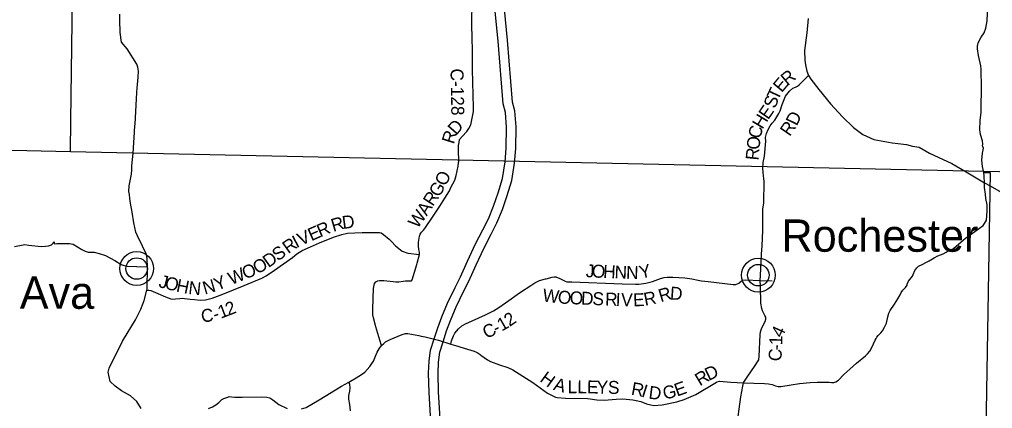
# Model space of a CAD drawing. Extents: x 0 to 34, y 0 to 22.
# Drawn here: x 24.277 to 28.547, y 13.16 to 14.868 of the extents above; entities that cross this region are included whole.
import ezdxf

# ---------------------------------------------------------------- set-up
doc = ezdxf.new("R2010")
doc.units = 0
for name, color, linetype in [('Default', 7, 'Continuous'), ('GM_X_County_Road', 7, 'Continuous'), ('GM_X_County_Road_Text', 7, 'Continuous'), ('GM_X_State_Route', 7, 'Continuous'), ('GM_X_Township', 7, 'Continuous'), ('GM_X_Unincorporated', 7, 'Continuous'), ('GM_X_Unincorporated_Text', 7, 'Continuous')]:
    doc.layers.add(name, color=color, linetype=linetype)

msp = doc.modelspace()

# ---------------------------------------------------------------- linework, layer by layer
at = {"layer": 'Default'}
for points in [[(28.5032, 14.3125), (28.5032, 14.3126), (28.5041, 14.3199), (28.5022, 14.335), (28.4942, 14.363), (28.4916, 14.3835), (28.493, 14.424), (28.4964, 14.4614), (28.4975, 14.4788), (28.4982, 14.5681), (28.497, 14.6499), (28.4955, 14.6639), (28.4856, 14.7097), (28.4811, 14.7392), (28.4811, 14.7513), (28.4837, 14.7653), (28.4973, 14.7899), (28.5094, 14.8088), (28.518, 14.8297), (28.5237, 14.8622), (28.5275, 14.9622)], [(26.2042, 14.2401), (26.2048, 14.2448), (26.2031, 14.2953), (26.2034, 14.3146), (26.2066, 14.3276), (26.2081, 14.3407), (26.2197, 14.3548), (26.2399, 14.3765), (26.2493, 14.3899), (26.2571, 14.4058), (26.2608, 14.4199), (26.2662, 14.4494), (26.2688, 14.4635), (26.2698, 14.482), (26.2656, 14.6481), (26.2646, 14.7424), (26.2636, 14.7768), (26.2626, 14.854), (26.2639, 14.943)], [(28.5119, 14.1501), (28.5105, 14.1807), (28.5081, 14.1966), (28.5023, 14.2231), (28.4995, 14.2499), (28.5028, 14.2814), (28.5066, 14.3028), (28.5032, 14.3125)], [(26.0228, 13.7982), (26.0229, 13.7985), (26.0329, 13.8366), (26.0329, 13.8461), (26.0297, 13.8582), (26.0277, 13.8744), (26.0284, 13.8896), (26.0309, 13.9078), (26.032, 13.9169), (26.0349, 13.9252), (26.0409, 13.934), (26.0503, 13.9431), (26.0589, 13.9542), (26.0899, 14.0002), (26.1213, 14.0489), (26.1434, 14.0839), (26.1639, 14.1159), (26.1699, 14.1296), (26.1873, 14.1621), (26.1931, 14.1827), (26.2021, 14.2237), (26.2042, 14.2401)], [(27.4545, 13.2725), (27.4579, 13.2805), (27.473, 13.3025), (27.5017, 13.3453), (27.5186, 13.3688), (27.5213, 13.3741), (27.5232, 13.3904), (27.5268, 13.4843), (27.5287, 13.4968), (27.5344, 13.5138), (27.5498, 13.5426), (27.5514, 13.5521), (27.5521, 13.5608), (27.5483, 13.5687), (27.5377, 13.5888), (27.5339, 13.5997), (27.5301, 13.6228), (27.5293, 13.6966), (27.5278, 13.7224), (27.5293, 13.7436), (27.5333, 13.8378), (27.536, 13.8745), (27.5389, 13.9415), (27.5392, 14.0346), (27.544, 14.0631), (27.5446, 14.1573), (27.544, 14.1704), (27.5425, 14.1812), (27.5399, 14.1968)], [(28.5158, 14.1005), (28.5121, 14.1308), (28.5119, 14.1501)], [(27.4545, 13.2725), (27.4995, 13.2711), (27.5463, 13.2693), (27.5644, 13.2682), (27.5796, 13.2652), (27.5951, 13.2603), (27.6064, 13.2572), (27.6177, 13.2569), (27.6631, 13.2634), (27.6993, 13.2699), (27.7473, 13.2737), (27.7772, 13.2764), (27.7991, 13.2761), (27.8293, 13.2754), (27.8407, 13.2739), (27.8509, 13.275), (27.8592, 13.2777), (27.8705, 13.2845), (27.8947, 13.3088), (27.9211, 13.3331), (27.9502, 13.3592), (27.9894, 13.3915), (27.9985, 13.4009), (28.0087, 13.4123), (28.0174, 13.4275), (28.0313, 13.4597), (28.0355, 13.468), (28.0389, 13.4733), (28.0453, 13.4809), (28.0574, 13.4923), (28.0645, 13.5006), (28.0732, 13.5169), (28.0815, 13.5355), (28.0879, 13.5623), (28.0924, 13.5786), (28.0973, 13.5904), (28.117, 13.6184), (28.1313, 13.6415), (28.1415, 13.6593), (28.1464, 13.6692), (28.1539, 13.6794), (28.1653, 13.6915), (28.1721, 13.7014), (28.1724, 13.7067), (28.1781, 13.7192), (28.1955, 13.7415), (28.1988, 13.748), (28.206, 13.7658), (28.2143, 13.7775), (28.2215, 13.7855), (28.2374, 13.7927), (28.2577, 13.8029), (28.2687, 13.8079), (28.291, 13.8215), (28.3065, 13.8299), (28.3189, 13.8352), (28.3303, 13.8394), (28.3439, 13.8466), (28.3526, 13.8519), (28.3665, 13.8584), (28.3756, 13.8629), (28.3877, 13.8735), (28.4285, 13.9077), (28.459, 13.9304), (28.49, 13.9513), (28.5055, 13.9638), (28.5123, 13.9729), (28.5205, 13.9874), (28.5224, 14.0065), (28.5233, 14.0275), (28.5233, 14.0542), (28.5181, 14.0814), (28.5158, 14.1005)], [(24.8361, 13.6794), (24.845, 13.68), (24.8533, 13.6781), (24.8837, 13.6652), (24.9181, 13.651), (24.9409, 13.6417), (24.9503, 13.6407), (24.9613, 13.6411), (24.9809, 13.6436), (24.9915, 13.6444), (25.0017, 13.643), (25.0149, 13.6416), (25.0259, 13.6405), (25.0452, 13.638), (25.0705, 13.6356), (25.0932, 13.6372), (25.123, 13.6447), (25.1689, 13.6617), (25.2627, 13.7007), (25.3407, 13.7323), (25.3596, 13.7423), (25.3956, 13.768), (25.4746, 13.8231), (25.4945, 13.8392), (25.5182, 13.8534), (25.5547, 13.8692), (25.5943, 13.8873), (25.6549, 13.9127), (25.6923, 13.9244), (25.7168, 13.9303), (25.7806, 13.9334), (25.8569, 13.9325), (25.8638, 13.9307), (25.8744, 13.9239), (25.8998, 13.9033), (25.9097, 13.8939), (25.9276, 13.8736), (25.9561, 13.8511), (25.9807, 13.8415), (26.0329, 13.8366)], [(24.255, 13.871), (24.293, 13.8792), (24.2991, 13.8801), (24.3188, 13.8774), (24.3726, 13.8715), (24.3911, 13.8723), (24.4043, 13.8736), (24.4178, 13.8784), (24.4299, 13.8915), (24.4298, 13.8832), (24.4404, 13.8841), (24.4971, 13.8851), (24.5043, 13.8834), (24.513, 13.8809), (24.5512, 13.8581), (24.5653, 13.8504), (24.5779, 13.8464), (24.5911, 13.8463), (24.6043, 13.8465), (24.6267, 13.8405), (24.6545, 13.8323), (24.6957, 13.8095), (24.7232, 13.793), (24.7316, 13.789), (24.7423, 13.7867), (24.7494, 13.7851), (24.7909, 13.7839), (24.8386, 13.7826)], [(25.8654, 13.4374), (25.858, 13.4604), (25.8413, 13.5194), (25.8309, 13.5579), (25.8278, 13.5707), (25.8272, 13.5931), (25.8288, 13.6438), (25.8311, 13.6874), (25.8355, 13.709), (25.8403, 13.7166), (25.8494, 13.7212), (25.8569, 13.7228), (25.8758, 13.7222), (25.9163, 13.718), (25.9291, 13.7165), (25.9423, 13.7163), (25.9612, 13.7198), (25.9706, 13.7207), (25.9873, 13.7208), (25.9948, 13.7201), (25.9971, 13.7212), (26.0005, 13.7251), (26.0211, 13.7919), (26.0228, 13.7982)], [(26.17, 13.4432), (26.1722, 13.4566), (26.1809, 13.4791), (26.1875, 13.4913), (26.2031, 13.5094), (26.2176, 13.5225), (26.2344, 13.5323), (26.3222, 13.5718), (26.3566, 13.5894), (26.3802, 13.6035), (26.4243, 13.6342), (26.4605, 13.6599), (26.4758, 13.6707), (26.5203, 13.7007), (26.5378, 13.7112), (26.5596, 13.7215), (26.5859, 13.7291), (26.5881, 13.7297)], [(26.5881, 13.7297), (26.6141, 13.7372), (26.6235, 13.7385), (26.6303, 13.7379), (26.6475, 13.7302), (26.6719, 13.719), (26.6787, 13.7168), (26.7014, 13.7165), (26.9215, 13.7076), (26.9809, 13.7056), (26.9948, 13.7066), (27.0254, 13.711), (27.0547, 13.7176), (27.0896, 13.7314), (27.1055, 13.7355), (27.1198, 13.7373), (27.1447, 13.7374), (27.1962, 13.7337), (27.2272, 13.7301), (27.2557, 13.7235), (27.2694, 13.7199), (27.2993, 13.7171), (27.4083, 13.705), (27.4208, 13.7052), (27.4332, 13.7104), (27.4459, 13.7201), (27.4518, 13.724), (27.4643, 13.7253), (27.5278, 13.7224)], [(27.5278, 13.7224), (27.5801, 13.72)], [(25.5146, 13.1582), (25.5347, 13.1647), (25.5924, 13.1985), (25.6906, 13.2577), (25.7224, 13.2759), (25.7548, 13.2949), (25.7786, 13.3093), (25.7922, 13.3199), (25.8145, 13.3449), (25.8239, 13.3574), (25.8311, 13.3681), (25.8394, 13.3893), (25.8473, 13.4078), (25.856, 13.4222), (25.8654, 13.4374), (25.8752, 13.4457), (25.8828, 13.4526), (25.9032, 13.4636), (25.9564, 13.4856), (25.9704, 13.4898), (25.9806, 13.4894), (26.0294, 13.4804), (26.0403, 13.478), (26.0403, 13.478)], [(26.0403, 13.478), (26.0566, 13.4744), (26.0683, 13.4718), (26.1162, 13.4597), (26.17, 13.4432), (26.1904, 13.4364), (26.2425, 13.4213), (26.2724, 13.4115), (26.2849, 13.4059), (26.2983, 13.3967), (26.2984, 13.3967)], [(26.2984, 13.3967), (26.3015, 13.3945), (26.3314, 13.3734), (26.3442, 13.3662), (26.3836, 13.3523), (26.4198, 13.3406), (26.4414, 13.33), (26.5291, 13.2745), (26.5941, 13.2273), (26.6172, 13.2152), (26.6289, 13.2103), (26.6372, 13.2081), (26.6735, 13.2062), (26.7699, 13.2041), (26.782, 13.2022), (26.8099, 13.1981), (26.8432, 13.1963), (26.8949, 13.2005), (26.9248, 13.2021), (26.969, 13.198), (26.983, 13.1953), (27.0034, 13.1908), (27.0291, 13.1814), (27.0469, 13.1765), (27.0601, 13.1739), (27.0967, 13.1762), (27.1613, 13.1888), (27.1938, 13.1994), (27.2456, 13.2215), (27.3358, 13.2758), (27.3392, 13.2773), (27.3491, 13.2803), (27.3978, 13.2755), (27.4545, 13.2725)], [(25.73, 13.1506), (25.7262, 13.1782), (25.722, 13.2017), (25.7217, 13.2078), (25.7228, 13.2172), (25.7269, 13.2358), (25.7288, 13.2509), (25.7265, 13.2649), (25.7224, 13.2759)], [(27.4241, 13.0703), (27.4425, 13.2112), (27.4511, 13.2578), (27.4545, 13.2725)], [(25.1062, 13.1599), (25.1239, 13.1675), (25.139, 13.177), (25.1526, 13.1872), (25.1583, 13.1929), (25.1658, 13.2001), (25.1734, 13.2046), (25.1908, 13.2107), (25.1968, 13.2122), (25.207, 13.2111), (25.2221, 13.2104), (25.2546, 13.2104), (25.3389, 13.2113), (25.3631, 13.2095), (25.3759, 13.2065), (25.3888, 13.1985), (25.4145, 13.1777), (25.4515, 13.16)]]:
    msp.add_lwpolyline(points, dxfattribs=at)
at = {"layer": 'GM_X_County_Road'}
msp.add_lwpolyline([(27.5399, 14.1968), (27.5398, 14.1975), (27.5396, 14.2134), (27.54, 14.2407), (27.5457, 14.2678), (27.5518, 14.3336), (27.5511, 14.3499), (27.5545, 14.3673), (27.562, 14.3855), (27.5707, 14.4007), (27.5805, 14.4132), (27.5911, 14.426), (27.6088, 14.4556), (27.6156, 14.4673), (27.6231, 14.4942), (27.6386, 14.5317), (27.6556, 14.5529), (27.6699, 14.5658), (27.682, 14.5704), (27.6907, 14.5753), (27.6986, 14.5814), (27.7171, 14.5995), (27.7398, 14.6223)], dxfattribs=at)
at = {"layer": 'GM_X_State_Route'}
for points in [[(26.0897, 12.974), (26.0747, 13.2305), (26.0725, 13.3149), (26.0742, 13.3676), (26.0805, 13.4164), (26.0964, 13.4661), (26.1123, 13.5144), (26.1302, 13.5623), (26.1557, 13.6232), (26.1882, 13.692), (26.2119, 13.738), (26.2435, 13.8076), (26.2788, 13.8837), (26.3097, 13.9438), (26.3345, 13.9933), (26.3576, 14.0485), (26.377, 14.1076), (26.3963, 14.1697), (26.4079, 14.2426), (26.4129, 14.3035), (26.4145, 14.3949), (26.4102, 14.4596), (26.3993, 14.4976), (26.3777, 14.7733), (26.3443, 15.1077)], [(26.1312, 12.9764), (26.1162, 13.2323), (26.1141, 13.3147), (26.1157, 13.3643), (26.1212, 13.4073), (26.1359, 13.4533), (26.1515, 13.5006), (26.1689, 13.547), (26.1937, 13.6063), (26.2255, 13.6736), (26.2493, 13.7198), (26.2813, 13.7902), (26.3162, 13.8655), (26.3468, 13.925), (26.3724, 13.9759), (26.3966, 14.034), (26.4166, 14.0949), (26.4369, 14.1603), (26.4492, 14.2376), (26.4545, 14.3014), (26.4561, 14.3959), (26.4514, 14.4667), (26.4404, 14.505), (26.4192, 14.7769), (26.3858, 15.111)], [(24.7697, 14.2083), (24.7708, 14.2253), (24.7757, 14.2814), (24.7808, 14.3493), (24.7838, 14.401), (24.785, 14.4089), (24.7921, 14.5479), (24.7942, 14.5684), (24.7953, 14.5823), (24.7979, 14.6139), (24.7995, 14.6402), (24.7958, 14.6583), (24.7918, 14.6711), (24.7493, 14.7395), (24.7246, 14.7685), (24.7184, 14.8109), (24.7174, 14.8651), (24.7179, 14.8913)], [(27.7378, 14.8727), (27.7316, 14.8094), (27.7224, 14.732), (27.723, 14.6896), (27.7257, 14.668), (27.7326, 14.6412), (27.7398, 14.6223), (27.7492, 14.6064), (27.784, 14.5599), (27.8354, 14.4973), (27.8883, 14.4403), (27.9365, 14.3936), (27.9779, 14.3627), (28.0257, 14.3413), (28.1064, 14.3262), (28.17, 14.3189), (28.1951, 14.3122), (28.2246, 14.3074), (28.2705, 14.2804), (28.3687, 14.2356), (28.4305, 14.1984), (28.5119, 14.1501), (28.536, 14.137), (28.6503, 14.0719)], [(24.8197, 13.6229), (24.8243, 13.6349), (24.8361, 13.6794), (24.8378, 13.6857), (24.8386, 13.7826), (24.8372, 13.8179), (24.8353, 13.8277), (24.8331, 13.8389), (24.8173, 13.8728), (24.8151, 13.8768), (24.8017, 13.9016), (24.7884, 13.9337), (24.7787, 13.9757), (24.771, 14.0223), (24.7649, 14.0615), (24.7617, 14.0814), (24.7593, 14.0991), (24.7576, 14.1121), (24.7588, 14.137), (24.7601, 14.1455), (24.7683, 14.189), (24.7697, 14.2083)], [(24.811, 13.1596), (24.7927, 13.1909), (24.7642, 13.2158), (24.7255, 13.238), (24.697, 13.2583), (24.6754, 13.2791), (24.6666, 13.319), (24.6703, 13.3372), (24.7285, 13.4559), (24.786, 13.5494), (24.8093, 13.5962), (24.8197, 13.6229)]]:
    msp.add_lwpolyline(points, dxfattribs=at)
at = {"layer": 'GM_X_Township'}
for p, q in [((24.5027, 14.424), (24.5114, 15.0682)), ((24.5006, 14.2876), (24.5027, 14.424)), ((23.5089, 14.3112), (24.5006, 14.2876)), ((24.5006, 14.2876), (30.697, 14.1555)), ((28.5367, 14.1959), (28.456, 9.6182)), ((28.5081, 14.1966), (28.5367, 14.1959)), ((28.5367, 14.1959), (28.5081, 14.1966))]:
    msp.add_line(p, q, dxfattribs=at)
at = {"layer": 'GM_X_Unincorporated'}
for centre, radius in [((24.7915, 13.7746), 0.0742), ((24.7915, 13.7746), 0.0471), ((27.5194, 13.7455), 0.0742), ((27.5194, 13.7455), 0.0471)]:
    msp.add_circle(centre, radius, dxfattribs=at)

# ---------------------------------------------------------------- texts
at = {"layer": 'GM_X_County_Road_Text'}
for s, rotation, p in [('C-128', 271.1062, (26.1684, 14.6521)), ('E', 50.0035, (27.6217, 14.5441)), ('R', 39.7046, (27.647, 14.5746)), ('T', 65.0949, (27.6059, 14.5089)), ('S', 70.4668, (27.5937, 14.4742)), ('E', 55.5539, (27.5624, 14.4249)), ('H', 58.8932, (27.5371, 14.3829)), ('D', 63.867, (27.6876, 14.3976)), ('D', 48.6523, (26.1934, 14.357)), ('C', 77.0893, (27.5285, 14.3419)), ('R', 55.4038, (27.6566, 14.3516)), ('R', 72.6895, (26.1826, 14.318)), ('O', 84.3006, (27.5238, 14.2941)), ('R', 84.5197, (27.5194, 14.2478)), ('O', 64.7446, (26.1475, 14.1329)), ('G', 57.6471, (26.1171, 14.084)), ('R', 56.8631, (26.0912, 14.0443)), ('A', 56.9167, (26.064, 14.0025)), ('D', 7.3713, (25.6962, 13.9479)), ('W', 54.0288, (26.0236, 13.9468)), ('E', 23.6966, (25.5578, 13.8941)), ('R', 23.2503, (25.5965, 13.9111)), ('R', 16.4499, (25.6539, 13.9352)), ('I', 27.965, (25.4927, 13.8632)), ('V', 24.1777, (25.5124, 13.8737)), ('R', 35.3725, (25.4564, 13.8372)), ('D', 35.3468, (25.3699, 13.776)), ('S', 35.1543, (25.4106, 13.8049)), ('O', 22.1968, (25.2676, 13.7263)), ('O', 28.7901, (25.3202, 13.7482)), ('J', 357.6291, (26.7611, 13.7367)), ('O', 357.6242, (26.7877, 13.7356)), ('Y', 12.385, (27.003, 13.7296)), ('W', 22.1138, (25.2066, 13.7016)), ('H', 357.6281, (26.8375, 13.7336)), ('N', 357.6279, (26.8874, 13.7315)), ('N', 358.6469, (26.9383, 13.7294)), ('J', 345.7633, (24.8851, 13.6937)), ('O', 345.8408, (24.911, 13.6871)), ('H', 348.2621, (24.9619, 13.6743)), ('N', 353.7904, (25.0166, 13.6632)), ('N', 16.2301, (25.0902, 13.66)), ('Y', 22.2968, (25.1443, 13.6761)), ('W', 353.1752, (26.5703, 13.6307)), ('O', 355.071, (26.6375, 13.6226)), ('O', 358.3354, (26.6908, 13.6182)), ('D', 357.8283, (26.7405, 13.6167)), ('S', 357.7996, (26.7904, 13.6148)), ('R', 357.7941, (26.846, 13.6127)), ('I', 357.8312, (26.8926, 13.6109)), ('V', 358.0127, (26.9161, 13.61)), ('E', 2.3302, (26.9706, 13.6083)), ('R', 10.6885, (27.0219, 13.611)), ('R', 16.7635, (27.0908, 13.6263)), ('D', 355.9567, (27.1301, 13.6391)), ('2', 21.5625, (25.1937, 13.5665)), ('C', 6.379, (25.0768, 13.5378)), ('1', 20.7833, (25.1603, 13.5538)), ('2', 34.5874, (26.4278, 13.5177)), ('-', 18.0411, (25.1353, 13.5456)), ('1', 29.6253, (26.3929, 13.4975)), ('C', 24.8665, (26.3253, 13.4651)), ('-', 26.8489, (26.3695, 13.4856)), ('4', 65.4531, (27.6236, 13.4671)), ('1', 87.9284, (27.6237, 13.4379)), ('C', 86.0979, (27.6196, 13.3662)), ('-', 88.0035, (27.6229, 13.4147)), ('H', 323.8521, (26.5567, 13.2818)), ('R', 31.271, (27.2627, 13.2571)), ('D', 25.5354, (27.3012, 13.2806)), ('A', 344.4167, (26.6169, 13.2427)), ('L', 0.8323, (26.6825, 13.227)), ('L', 358.8814, (26.7244, 13.2276)), ('E', 358.8771, (26.7668, 13.2268)), ('Y', 358.8796, (26.8092, 13.226)), ('S', 358.8786, (26.859, 13.225)), ('E', 19.7885, (27.1625, 13.2121)), ('R', 349.9692, (26.9585, 13.2211)), ('I', 342.2562, (27.0024, 13.2135)), ('D', 352.6509, (27.0355, 13.2039)), ('G', 13.2592, (27.1071, 13.1987))]:
    msp.add_text(s, height=0.0567, rotation=rotation, dxfattribs=at).set_placement(p)
at = {"layer": 'GM_X_Unincorporated_Text'}
for s, p in [('Rochester', (27.6208, 13.8483)), ('Ava', (24.2783, 13.598))]:
    msp.add_text(s, height=0.14175, rotation=0, dxfattribs=at).set_placement(p)

doc.saveas('drawing.dxf')
